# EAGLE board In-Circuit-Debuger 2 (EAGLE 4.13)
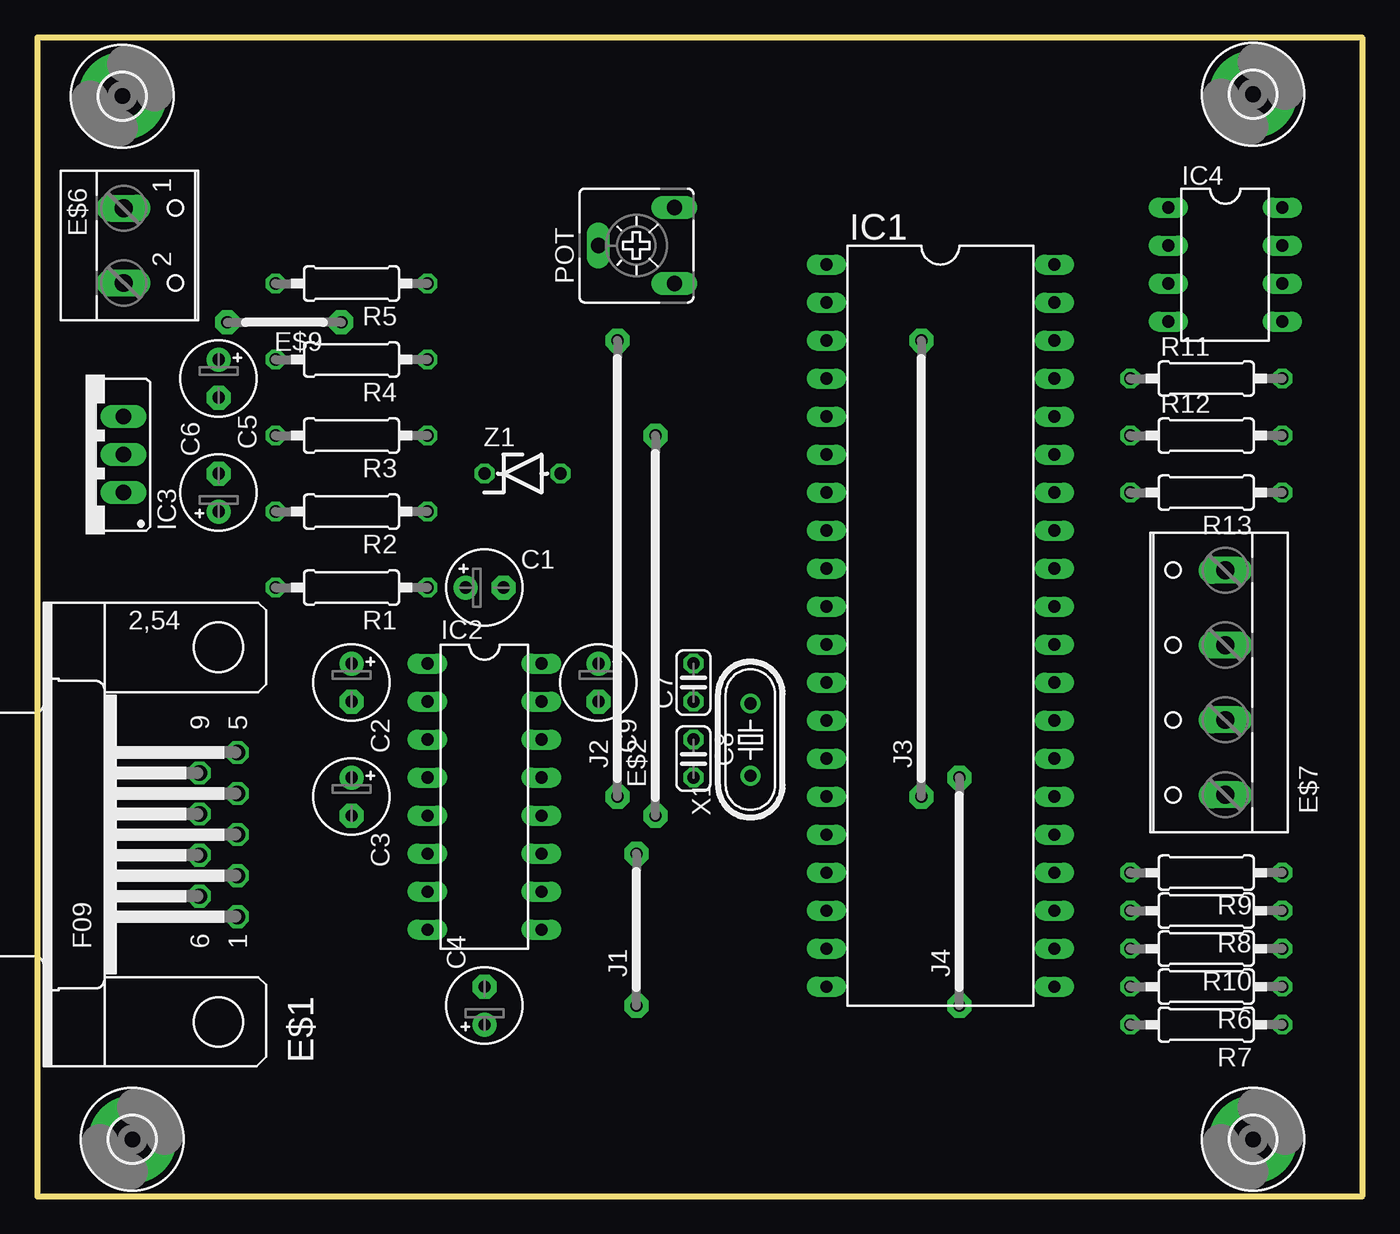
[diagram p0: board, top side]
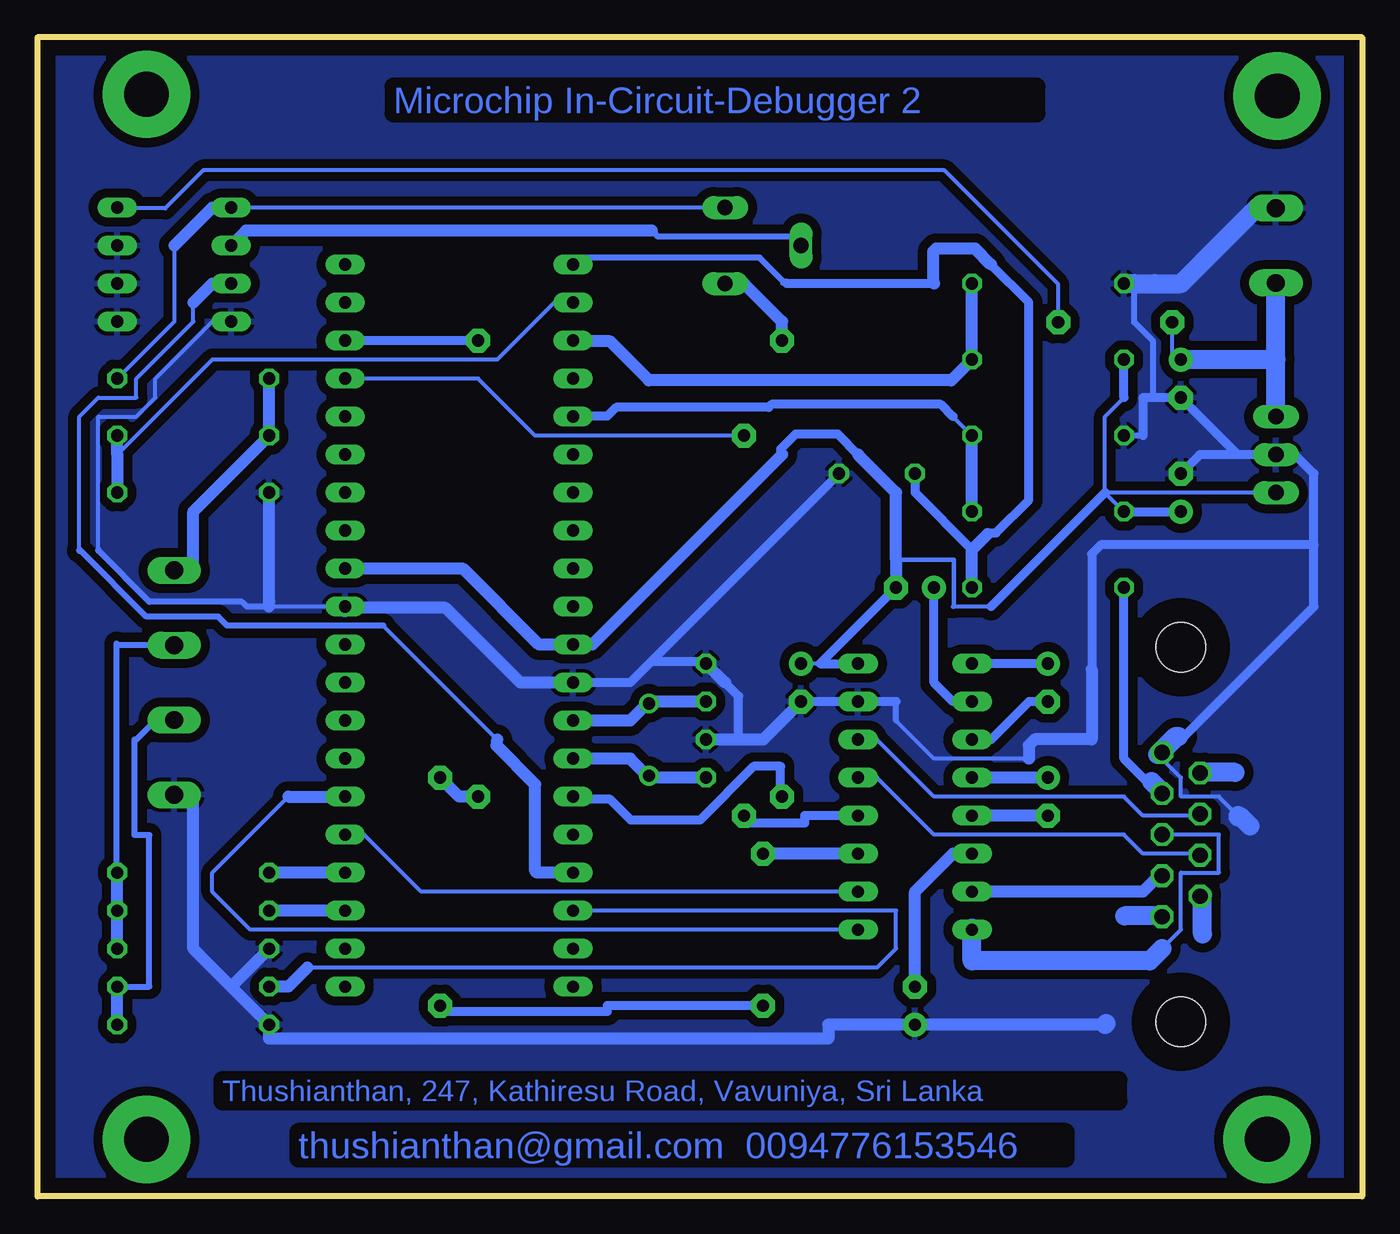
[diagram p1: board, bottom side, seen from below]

Size 88.57 x 77.46 mm. Coordinates in mm from the lower left corner, seen from the top.
Outline: 0,0 88.57,0 88.57,77.46 0,77.46 0,0
Copper layers (1*16): Top 0.035mm / dielectric 1.5mm / Bottom 0.035mm
Design rules "default": minimum track width 10mil, minimum drill 24mil, track to track 8mil, track to pad 8mil, pad to pad 8mil, via to via 8mil, smd to smd 8mil, copper to edge 40mil, drill to drill 8mil, minimum pad ring 10mil, minimum via ring 8mil, stop-mask expansion 4mil, vias tented up to drill 0mil, thermal gap 10mil

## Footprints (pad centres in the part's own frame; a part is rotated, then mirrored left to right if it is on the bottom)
E2,5-5 = drill 0.813 pad 1.6 round: + -1.27,0 | drill 0.813 pad 1.6 octagon: - 1.27,0
C025-024X044 = drill 0.813 octagon: 1 -1.27,0; 2 1.27,0
F09H = drill 1.016 octagon: 1 -5.486,-1.27; 2 -2.743,-1.27; 3 0,-1.27; 4 2.743,-1.27; 5 5.486,-1.27; 6 -4.115,1.27; 7 -1.372,1.27; 8 1.372,1.27; 9 4.115,1.27 | hole 3.302: -12.522,0; 12.522,0
25 = drill 0.813 pad 1.6 octagon: 1 -12.7,0; 2 12.7,0
3,0-PAD = drill 3 pad 5.842 round: B3,0 0,0
W237-102 = drill 1.194 long: 1 -2.5,-1.27; 2 2.5,-1.27
W237-4 = drill 1.194 long: 1 -7.5,-1.27; 2 -2.5,-1.27; 3 2.5,-1.27; 4 7.5,-1.27
07 = drill 0.813 pad 1.6 octagon: 1 -3.81,0; 2 3.81,0
DIL40 = drill 0.813 long: 1 -24.13,-7.62; 2 -21.59,-7.62; 3 -19.05,-7.62; 4 -16.51,-7.62; 5 -13.97,-7.62; 6 -11.43,-7.62; 7 -8.89,-7.62; 8 -6.35,-7.62; 9 -3.81,-7.62; 10 -1.27,-7.62; 11 1.27,-7.62; 12 3.81,-7.62; 13 6.35,-7.62; 14 8.89,-7.62; 15 11.43,-7.62; 16 13.97,-7.62; 17 16.51,-7.62; 18 19.05,-7.62; 19 21.59,-7.62; 20 24.13,-7.62; 21 24.13,7.62; 22 21.59,7.62; 23 19.05,7.62; 24 16.51,7.62; 25 13.97,7.62; 26 11.43,7.62; 27 8.89,7.62; 28 6.35,7.62; 29 3.81,7.62; 30 1.27,7.62; 31 -1.27,7.62; 32 -3.81,7.62; 33 -6.35,7.62; 34 -8.89,7.62; 35 -11.43,7.62; 36 -13.97,7.62; 37 -16.51,7.62; 38 -19.05,7.62; 39 -21.59,7.62; 40 -24.13,7.62
DIL16 = drill 0.813 long: 1 -8.89,-3.81; 2 -6.35,-3.81; 3 -3.81,-3.81; 4 -1.27,-3.81; 5 1.27,-3.81; 6 3.81,-3.81; 7 6.35,-3.81; 8 8.89,-3.81; 9 8.89,3.81; 10 6.35,3.81; 11 3.81,3.81; 12 1.27,3.81; 13 -1.27,3.81; 14 -3.81,3.81; 15 -6.35,3.81; 16 -8.89,3.81
78XXS = drill 1.016 long: GND 0,-2.54; IN -2.54,-2.54; OUT 2.54,-2.54
DIL08 = drill 0.813 long: 1 -3.81,-3.81; 2 -1.27,-3.81; 3 1.27,-3.81; 4 3.81,-3.81; 5 3.81,3.81; 6 1.27,3.81; 7 -1.27,3.81; 8 -3.81,3.81
10 = drill 0.813 pad 1.6 octagon: 1 -5.08,0; 2 5.08,0
30 = drill 0.813 pad 1.6 octagon: 1 -15.24,0; 2 15.24,0
15 = drill 0.813 pad 1.6 octagon: 1 -7.62,0; 2 7.62,0
CA6V = drill 1.016 long: A -2.54,-2.54; E 2.54,-2.54; S 0,2.54
0207/10 = drill 0.813 octagon: 1 -5.08,0; 2 5.08,0
HC49/S = drill 0.813 round: 1 -2.413,0; 2 2.413,0
ZDIO-5 = drill 0.813 octagon: A 2.54,0; C -2.54,0

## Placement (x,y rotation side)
C1  1uf  [E2,5-5]  29.89,40.69 0 top
C2  1uf  [E2,5-5]  21,34.34 270 top
C3  1uf  [E2,5-5]  21,26.72 270 top
C4  1uf  [E2,5-5]  29.89,12.75 90 top
C5  4.7u  [E2,5-5]  12.11,54.66 270 top
C6  4.7u  [E2,5-5]  12.11,47.04 90 top
C7  33p  [C025-024X044]  43.86,34.34 90 top
C8  33p  [C025-024X044]  43.86,29.26 270 top
C9  1uf  [E2,5-5]  37.51,34.34 270 top
E$1  [F09H]  12.11,24.18 90 top
E$2  [25]  41.32,38.15 90 top
E$3  [3,0-PAD]  5.68,73.54 0 top
E$4  [3,0-PAD]  6.35,3.81 0 top
E$5  [3,0-PAD]  81.28,3.81 0 top
E$6  [W237-102]  7.03,63.55 270 top
E$7  [W237-4]  78.15,34.34 90 top
E$8  [3,0-PAD]  81.28,73.66 0 top
E$9  [07]  16.51,58.42 180 top
IC1  PIC16F877A  [DIL40]  60.37,38.15 270 top
IC2  MAX232  [DIL16]  29.89,26.72 270 top
IC3  7805  [78XXS]  3.22,49.58 90 top
IC4  LM358  [DIL08]  79.42,62.28 270 top
J1  [10]  40.05,17.83 90 top
J2  [30]  38.78,41.96 90 top
J3  [30]  59.1,41.96 90 top
J4  [15]  61.64,20.37 90 top
POT  47K  [CA6V]  40.05,63.55 90 top
R1  1K  [0207/10]  21,40.69 180 top
R2  4.7K  [0207/10]  21,45.77 180 top
R3  6.8K  [0207/10]  21,50.85 180 top
R4  4.7K  [0207/10]  21,55.93 180 top
R5  4,7K  [0207/10]  21,61.01 180 top
R6  330  [0207/10]  78.15,14.02 180 top
R7  4.7K  [0207/10]  78.15,11.48 180 top
R8  330  [0207/10]  78.15,19.1 180 top
R9  330  [0207/10]  78.15,21.64 180 top
R10  4.7K  [0207/10]  78.15,16.56 180 top
R11  33  [0207/10]  78.15,54.66 0 top
R12  6.8K  [0207/10]  78.15,50.85 0 top
R13  2.2K  [0207/10]  78.15,47.04 180 top
X1  20MHz  [HC49/S]  47.67,30.53 90 top
Z1  5.1V  [ZDIO-5]  32.43,48.31 0 top

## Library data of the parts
C1-C9 R1-R13 = rcl
E$1 = con-subd
E$2 E$9 J1-J4 = jumper
E$3-E$5 E$8 = holes
E$6 E$7 = con-wago-500
IC1 = microchip
IC2 = maxim
IC3 = v-reg
IC4 = ic-package
POT = pot
X1 = crystal
Z1 = diode

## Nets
2: E$1.2 IC2.7
3: E$1.3 IC2.8
4: E$1.4 R1.2
7: E$1.7 IC2.13
8: E$1.8 IC2.14
GND: C4.+ C5.- C6.- C7.2 C8.1 C9.- E$1.5 E$6.1 E$7.1 IC1.12 IC1.31 IC2.15 IC3.GND IC4.4 IC4.5 IC4.6 IC4.7 R3.2 R5.2 R7.2 R10.2 R13.2 Z1.A
MCLR: IC1.1 R1.1 Z1.C
RA0: E$7.4 R11.1 R12.1
RA3: IC1.5 R2.1 R3.1
RB4: E$2.2 IC1.37
RB5: IC2.11 J1.2
RC3: IC1.18 R6.2
RC4: IC1.23 R8.2
RC5: IC1.24 R9.2
RC6: IC1.25 IC2.10
RC7: IC1.26 IC2.9
S$1: C2.+ IC2.1
S$2: C2.- IC2.3
S$3: C1.+ IC2.2
S$4: IC1.17 IC4.3
S$5: C3.+ IC2.4
S$6: C3.- IC2.5
S$7: C4.- IC2.6
S$8: E$2.1 IC2.12
S$14: E$9.1 IC4.8
S$15: IC1.3 R4.1 R5.1
S$18: IC1.38 J3.2
S$20: J1.1 J4.1
S$21: IC4.2 POT.S
S$22: C7.1 IC1.13 X1.2
S$23: C8.2 IC1.14 X1.1
S$25: E$7.2 R6.1 R7.1
S$28: E$7.3 R8.1 R9.1 R10.1
S$29: IC4.1 POT.E R11.2
S$30: J2.2 POT.A
S$33: IC1.2 R12.2 R13.1
S$34: J3.1 J4.2
S$35: IC1.15 J2.1
VDD: C1.- C6.+ C9.+ IC1.11 IC1.32 IC2.16 IC3.IN R2.2 R4.2
VIN: C5.+ E$6.2 E$9.2 IC3.OUT

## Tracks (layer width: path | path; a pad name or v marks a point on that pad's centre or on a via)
2
  Bottom 0.254: E$1.2 13.38,21.64
  Bottom 0.813: 13.38,21.64 14.65,20.37 IC2.7
3
  Bottom 0.254: 13.38,16.56 12.11,17.83 12.11,21.64 9.57,21.64 9.57,24.18 E$1.3
  Bottom 1.27: 13.38,16.56 14.2,15.74 26.08,15.74 IC2.8 | IC2.8 26.08,17.94 | IC2.8 26.08,17.74
4
  Bottom 0.254: E$1.4 13.38,26.72
  Bottom 0.61: R1.2 15.92,29.26 13.38,26.72
7
  Bottom 0.254: IC2.13 32.43,27.99 28.62,24.18 15.92,24.18 14.65,22.91 10.84,22.91 E$1.7
8
  Bottom 0.254: IC2.14 32.43,30.53 28.62,26.72 15.92,26.72 14.65,25.45 10.84,25.45 E$1.8
GND
  Bottom 0.254: 84.5,43.23 84.5,52.12 81.96,52.12 80.69,53.39 80.69,54.66 76.88,58.47 IC4.4 | 73.08,39.42 IC1.31 65.45,39.42 | 7.03,66.09 E$6.1 | 78.15,26.72 E$7.1 | 8.3,25.45 9.57,26.72 12.11,26.72 12.11,27.99 13.38,29.26 E$1.5 | 31.16,31.8 28.62,29.26 22.27,29.26
  Bottom 0.406: 31.16,31.8 31.16,33.07 | 14.65,50.85 R3.2 | 13.88,61.01 13.88,61.14 | 73.08,39.42 74.56,39.42 74.88,39.74 81.08,39.74 84.48,43.14 84.5,43.14 84.5,43.23 | 13.88,53.39 13.97,53.39 13.97,57.15 15.24,58.42 15.24,61.01
  Bottom 0.61: C9.- IC2.15 31.16,33.07 | 48.94,34.34 IC1.12 | 48.94,34.34 Z1.A | 8.3,49.58 10.84,49.58 C6.- | 8.3,49.58 IC3.GND 4.49,49.58 3.22,48.31 3.22,43.54 | 13.38,29.26 3.22,39.42 3.22,43.54 | 8.3,49.58 C5.- 13.88,53.39 14.65,53.39 14.65,50.85 | 42.59,34.34 41.68,33.43 41.68,30.53 | C7.2 43.88,35.54 43.88,35.74 47.54,35.74 48.94,34.34 | 18.08,35.23 18.08,42.94 17.48,43.54 3.22,43.54
  Bottom 0.813: C8.1 41.68,30.53 40.05,30.53 C9.- | 42.59,34.34 C7.2 | 75.61,14.02 78.15,16.56 78.15,26.72 | 75.61,14.02 R7.2 73.08,10.54 35.68,10.54 35.68,11.48 C4.+ 17.19,11.48 | 75.61,14.02 R10.2 | IC1.12 56.28,34.34 61.28,39.34 67.88,39.34 68.08,39.14 67.99,39.14 IC1.31 | 73.08,39.42 73.08,39.74 73.07,39.75 R13.2 | 22.27,29.26 22.28,29.27 22.28,30.14 21.88,30.54 18.08,30.54 18.08,35.23
  Bottom 1.27: R5.2 15.24,61.01 13.88,61.01 12.11,61.01 7.03,66.09 | 17.19,11.48 17.13,11.54 | 8.3,25.45 8.28,25.34 8.08,25.34 7.48,24.74
  pour Bottom (isolate 0.61): -0.32,77.11 -0.32,0 87.95,0 87.95,77.11
MCLR
  Bottom 0.254: 38.48,61.01 38.78,61.01 | 25.02,44.28 24.81,44.5
  Bottom 0.406: IC1.1 52.29,62.74 40.28,62.74 38.68,61.14 38.48,61.14 38.48,61.01 38.48,60.94
  Bottom 0.61: 28.62,61.01 38.48,61.01 | 24.81,62.28 22.28,59.75 22.28,46.54 24.48,44.34 25.08,44.34 25.02,44.28 | Z1.C 29.88,48.34 29.88,47.03 26.08,43.23
  Bottom 0.813: R1.1 26.08,43.23 25.02,44.28 | 24.81,62.28 25.87,63.34 28.48,63.34 28.68,63.14 28.68,61.14 28.62,61.01
RA0
  Bottom 0.813: R11.1 R12.1 78.15,45.77 78.15,41.96 E$7.4
RA3
  Bottom 0.254: R3.1 27.35,52.12
  Bottom 0.61: 27.35,52.12 28.17,52.94 39.48,52.94 39.68,52.74 49.88,52.74 50.48,52.14 52.68,52.14 IC1.5
  Bottom 0.813: R2.1 R3.1
RB4
  Bottom 0.254: E$2.2 55.29,50.85 59.1,54.66 IC1.37
RB5
  Bottom 0.813: IC2.11 J1.2
RC3
  Bottom 0.254: 70.53,15.29 32.43,15.29 31.16,16.56 31.16,19.1 IC1.18
  Bottom 0.813: R6.2 71.8,14.02 70.53,15.29
RC4
  Bottom 0.813: IC1.23 R8.2
RC5
  Bottom 0.813: IC1.24 R9.2
RC6
  Bottom 0.254: IC2.10 62.91,20.37 66.72,24.18 IC1.25
RC7
  Bottom 0.254: 71.8,26.72 76.88,21.64 76.88,20.37 74.34,17.83 IC2.9
  Bottom 0.813: 71.8,26.72 IC1.26
S$1
  Bottom 0.61: C2.+ IC2.1
S$2
  Bottom 0.61: C2.- 22.27,33.07 24.81,30.53 IC2.3
S$3
  Bottom 0.61: C1.+ 28.62,34.34 27.35,33.07 IC2.2
S$4
  Bottom 0.254: 57.83,30.53 65.45,38.15 | 85.77,43.23 85.77,52.12 84.5,53.39 81.96,53.39 81.96,54.66 78.15,58.47 78.15,59.74 | IC1.17 54.02,21.64 | 76.88,61.01 IC4.3
  Bottom 0.406: 65.45,38.15 75.89,38.15 76.48,38.74 81.28,38.74 85.68,43.14 85.77,43.14 85.77,43.23
  Bottom 0.813: 78.15,59.74 76.88,61.01 | 54.02,21.64 55.18,21.64 55.28,21.74 55.28,27.54 57.88,30.14 57.83,30.14 57.83,30.53
S$5
  Bottom 0.813: C3.+ IC2.4
S$6
  Bottom 0.813: C3.- IC2.5
S$7
  Bottom 0.813: C4.- 29.89,20.37 27.35,22.91 IC2.6
S$8
  Bottom 0.61: IC2.12 37.28,25.45 37.28,24.94 41.28,24.94 41.28,25.45 | 41.28,25.45 41.28,25.54 | 41.28,25.45 E$2.1
S$9
  Bottom 1.27: 8.48,28.34 10.68,28.34
S$10
  Bottom 1.27: 10.68,17.54 10.68,20.14
S$11
  Bottom 1.27: 13.48,27.14 14.08,27.74
S$12
  Bottom 1.27: 13.48,18.74 15.88,18.74
S$13
  Bottom 1.27: 13.68,29.54 12.48,30.74 12.28,30.74
S$14
  Bottom 0.254: E$9.1 20.32,60.96 27.94,68.58 77.47,68.58 80.01,66.04 82.55,66.04 IC4.8
S$15
  Bottom 0.813: R5.1 R4.1 27.47,54.54 47.68,54.54 50.28,57.14 52.68,57.14 IC1.3
S$18
  Bottom 0.61: J3.2 IC1.38
S$20
  Bottom 0.61: J1.1 50.48,12.75 50.48,12.34 61.68,12.34 61.68,12.75 J4.1
S$21
  Bottom 0.406: 47.48,64.54 47.08,64.14 37.48,64.14 37.28,63.94 37.28,63.54 37.48,63.54 POT.S
  Bottom 0.813: IC4.2 74.62,64.54 47.48,64.54
S$22
  Bottom 0.254: 47.67,33.07 X1.2
  Bottom 0.813: C7.1 47.67,33.07 48.94,31.8 IC1.13
S$23
  Bottom 0.254: 47.67,27.99 X1.1
  Bottom 0.813: C8.2 47.67,27.99 48.94,29.26 IC1.14
S$25
  Bottom 0.406: E$7.2 80.69,31.8 81.96,30.53 82.08,30.53 82.08,24.14 81.08,24.14 81.08,14.02 R6.1
  Bottom 0.813: R7.1 R6.1
S$28
  Bottom 0.406: 80.69,36.88 83.22,36.88 83.28,36.94 83.28,21.94 83.48,21.74 83.48,21.64 R9.1
  Bottom 0.813: R10.1 R8.1 R9.1 | 80.69,36.88 E$7.3
S$29
  Bottom 0.254: POT.E IC4.1 | R11.2 79.42,58.47 79.42,63.55
  Bottom 0.813: 79.42,63.55 76.88,66.09 IC4.1
S$30
  Bottom 0.254: 41.32,61.01 POT.A
  Bottom 0.813: 41.32,61.01 38.78,58.47 J2.2
S$33
  Bottom 0.254: 83.23,49.58 76.88,55.93 57.83,55.93 54.02,59.74 IC1.2
  Bottom 0.813: R12.2 83.23,49.58 R13.1
S$34
  Bottom 0.813: J3.1 60.37,26.72 J4.2
S$35
  Bottom 0.61: J2.1 38.88,26.72 38.88,28.74 40.68,28.74 44.28,25.14 48.88,25.14 50.28,26.54 52.68,26.54 52.68,26.74 IC1.15
VDD
  Bottom 0.254: IC1.32 66.72,41.96 | 51.48,36.88 IC1.11 | 36.24,35.61 C9.+ | 24.81,39.42 27.35,39.42 | 15.92,53.39 17.19,52.12 17.19,47.04 | 17.19,47.04 R2.2 | IC3.IN 17.19,47.04
  Bottom 0.305: 31.16,42.54 27.28,42.54 27.28,39.42 27.35,39.42
  Bottom 0.61: 38.85,49.51 38.88,49.54 38.88,49.94 37.88,50.94 35.06,50.94 33.7,49.58 | IC2.16 36.24,35.61 C1.- | 15.92,53.39 R4.2 | R2.2 C6.+ | 17.19,47.04 24.81,39.42
  Bottom 0.813: IC1.32 67.68,41.96 67.68,41.94 60.08,41.94 55.02,36.88 IC1.11 | 51.48,36.88 38.85,49.51 38.78,49.58 | 33.7,49.58 31.16,47.04 31.16,42.54 C1.-
VIN
  Bottom 0.254: E$9.2 12.7,55.88 C5.+
  Bottom 1.27: IC3.OUT 5.76,55.93 | 5.76,55.93 E$6.2 | 5.76,55.93 C5.+

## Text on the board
Bottom: Microchip In-Circuit-Debugger 2 | Thushianthan, 247, Kathiresu Road, Vavuniya, Sri Lanka | thushianthan@gmail.com 0094776153546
